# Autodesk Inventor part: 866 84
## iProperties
Created: 2005-11
Part Number: 866 84
Material: 1.4301 X5CrNi10-10 A2
Description: Flansch KF 40 (lang)
Document SubType Name: Modellieren
Designer: Mittelmeyer
Manufacturer: Standard
Standards Organization: Custom
Author: Mittelmeyer
Comments: LEYBOLD
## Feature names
1. Extrusion2
2. Drehung1 [Revolution]
3. Bohrung1 [Hole]
